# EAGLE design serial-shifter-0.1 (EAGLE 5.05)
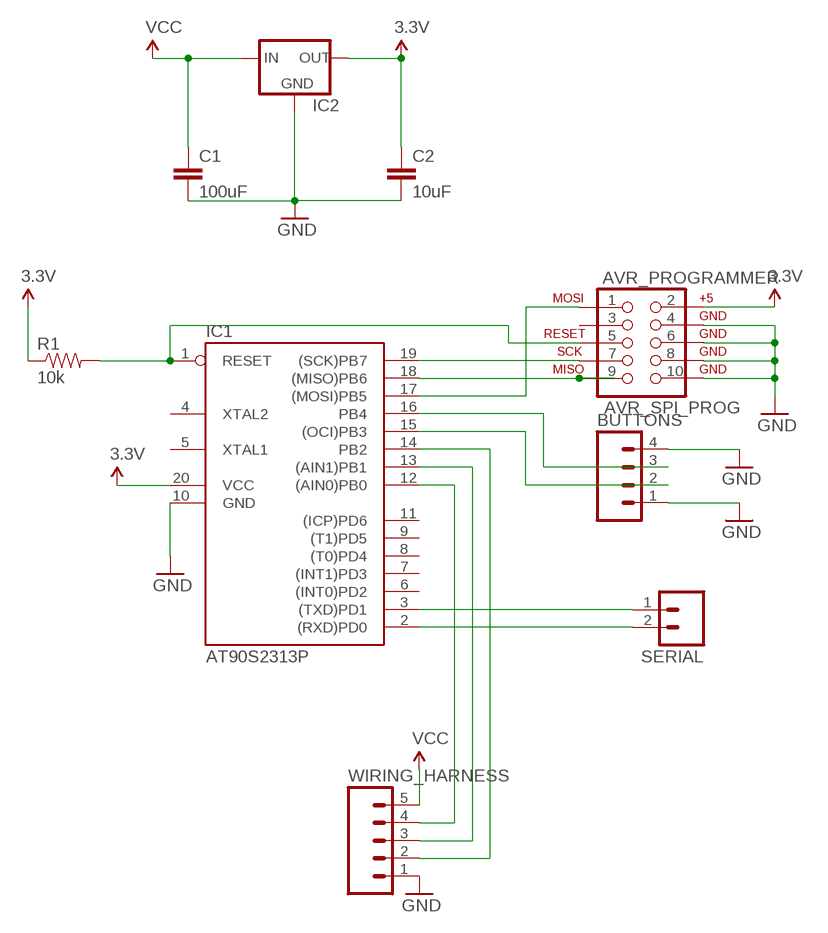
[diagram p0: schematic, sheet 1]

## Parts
AVR_PROGRAMMER  AVR_SPI_PROG  [AVR_ICSP]
BUTTONS  M04PTH  [1X04]
C1  100uF  CAP_  [AXIAL-5MM]
C2  10uF  CAP_  [AXIAL-5MM]
IC1  AT90S2313P  [DIL20]
IC2  V_REG_78XXSINK  [TO220-IGO]
R1  10k  RESISTORPTH1  [AXIAL-0.3]
SERIAL  M02PTH  [1X02]
WIRING_HARNESS  M05PTH  [1X05]

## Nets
3.3V: AVR_PROGRAMMER.2 C2.P$1 IC1.20(VCC) IC2.OUT R1.P$1
AVR_2313A: AVR_PROGRAMMER.5 IC1.1(RESET) R1.P$2
GND: AVR_PROGRAMMER.4 AVR_PROGRAMMER.6 AVR_PROGRAMMER.8 AVR_PROGRAMMER.10 BUTTONS.1 BUTTONS.4 C1.P$2 C2.P$2 IC1.10(GND) IC2.GND WIRING_HARNESS.1
N$1: BUTTONS.3 IC1.16(PB4)
N$2: AVR_PROGRAMMER.1 IC1.17((MOSI)PB5)
N$3: AVR_PROGRAMMER.9 IC1.18((MISO)PB6)
N$4: AVR_PROGRAMMER.7 IC1.19((SCK)PB7)
N$5: IC1.3((TXD)PD1) SERIAL.1
N$6: IC1.2((RXD)PD0) SERIAL.2
N$7: BUTTONS.2 IC1.15((OCI)PB3)
N$8: IC1.12((AIN0)PB0) WIRING_HARNESS.4
N$9: IC1.13((AIN1)PB1) WIRING_HARNESS.3
N$10: IC1.14(PB2) WIRING_HARNESS.2
VCC: C1.P$1 IC2.IN WIRING_HARNESS.5
Unconnected: AVR_PROGRAMMER.3 IC1.4(XTAL2) IC1.5(XTAL1) IC1.6((INT0)PD2) IC1.7((INT1)PD3) IC1.8((T0)PD4) IC1.9((T1)PD5) IC1.11((ICP)PD6)

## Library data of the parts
AVR_PROGRAMMER = SparkFun:AVR_SPI_PROG: AVR ICSP Header This is the standard AVR In Circuit Serial Programming header. Minimal, but includes pin one indicator. Works with standard Olimex programmers. Also look for the 6-pin reduced version. Spark Fun Electronics SKU: PRT-00778
BUTTONS = SparkFun:M04: Header 4 Standard 4-pin 0.1" header. Use with straight break away headers (SKU : PRT-00116), right angle break away headers (PRT-00553), swiss pins (PRT-00743), machine pins (PRT-00117), and female headers (PRT-00115). Molex polarized connector foot print use with SKU : PRT-08231 with associated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
C1 C2 = SparkFun:CAP: Capacitor
IC1 = atmel:AT90S2313: MICROCONTROLLER 2 Kbytes FLASH 128 bytes SRAM 128 bytes EEPROM UART
IC2 = SparkFun:V_REG_78XX: Voltage Regulator Standard 7805 5V regulator. IGO (Input Ground Output). Spark Fun Electronics SKU : COM-00107
R1 = SparkFun:RESISTOR: Resistor
SERIAL = SparkFun:M02: Header 2
WIRING_HARNESS = SparkFun:M05: Header 5 Standard 5-pin 0.1" header. Use with straight break away headers (SKU : PRT-00116), right angle break away headers (PRT-00553), swiss pins (PRT-00743), machine pins (PRT-00117), and female headers (PRT-00115). Molex polarized connector foot print use with SKU : PRT-08230 with associated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

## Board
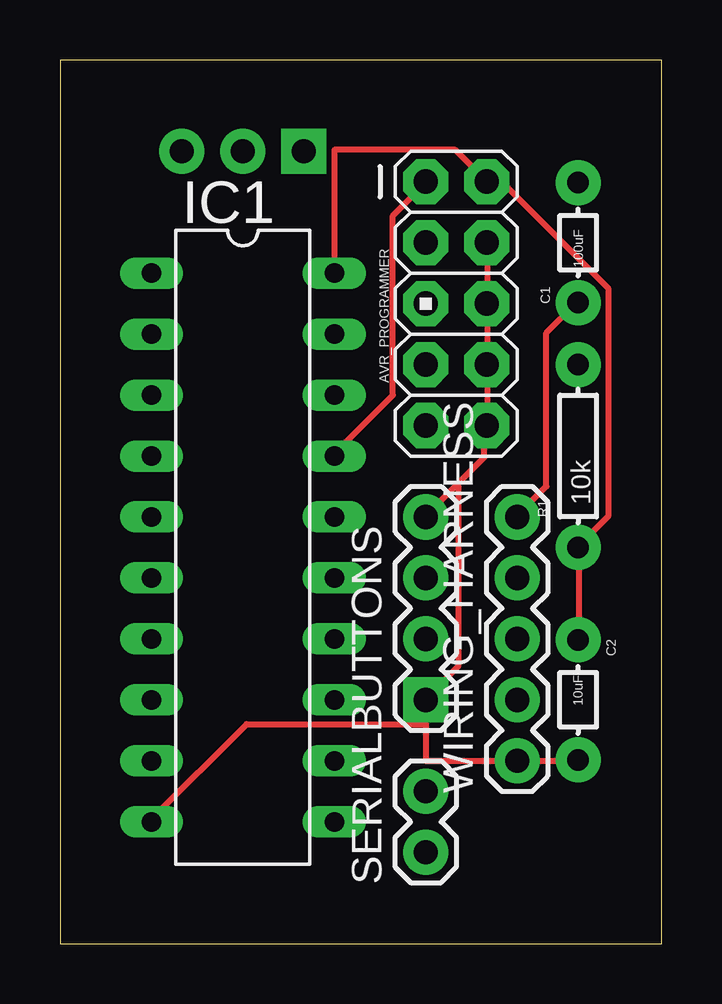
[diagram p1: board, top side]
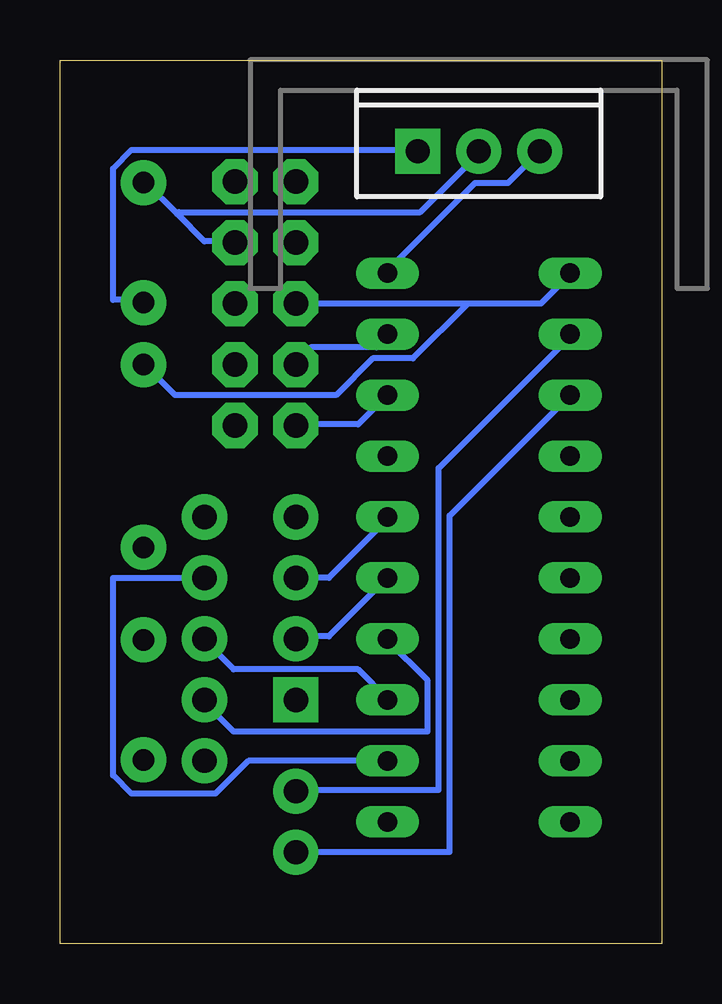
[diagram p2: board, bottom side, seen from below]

Size 25.07 x 36.82 mm. Coordinates in mm from the lower left corner, seen from the top.
Outline: 0,0 25.07,0 25.07,36.82 0,36.82 0,0
Copper layers (1*16): Top 0.035mm / dielectric 1.5mm / Bottom 0.035mm
Design rules "default": minimum track width 10mil, minimum drill 24mil, track to track 8mil, track to pad 8mil, pad to pad 8mil, via to via 8mil, smd to smd 8mil, copper to edge 40mil, drill to drill 8mil, minimum pad ring 10mil, minimum via ring 8mil, stop-mask expansion 4mil, vias tented up to drill 0mil, thermal gap 10mil

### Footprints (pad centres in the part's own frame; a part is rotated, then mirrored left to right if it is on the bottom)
AVR_ICSP = drill 1.016 pad 1.88 octagon: 1 -1.27,5.08; 2 1.27,5.08; 3 -1.27,2.54; 4 1.27,2.54; 5 -1.27,0; 6 1.27,0; 7 -1.27,-2.54; 8 1.27,-2.54; 9 -1.27,-5.08; 10 1.27,-5.08
1X04 = drill 1.016 pad 1.88 square: 1 0,0 | drill 1.016 pad 1.88 round: 2 2.54,0; 3 5.08,0; 4 7.62,0
AXIAL-5MM = drill 0.9 pad 1.88 round: P$1 -2.5,0; P$2 2.5,0
DIL20 = drill 0.813 long: 1 -11.43,-3.81; 2 -8.89,-3.81; 3 -6.35,-3.81; 4 -3.81,-3.81; 5 -1.27,-3.81; 6 1.27,-3.81; 7 3.81,-3.81; 8 6.35,-3.81; 9 8.89,-3.81; 10 11.43,-3.81; 11 11.43,3.81; 12 8.89,3.81; 13 6.35,3.81; 14 3.81,3.81; 15 1.27,3.81; 16 -1.27,3.81; 17 -3.81,3.81; 18 -6.35,3.81; 19 -8.89,3.81; 20 -11.43,3.81
TO220-IGO = drill 1 pad 1.88 round: GND 0,0; OUT 2.54,0 | drill 1 pad 1.88 square: IN -2.54,0
AXIAL-0.3 = drill 0.9 pad 1.88 round: P$1 -3.81,0; P$2 3.81,0
1X02 = drill 1.016 pad 1.88 round: 1 0,0; 2 2.54,0
1X05 = drill 1.016 pad 1.88 round: 1 0,0; 2 2.54,0; 3 5.08,0; 4 7.62,0; 5 10.16,0

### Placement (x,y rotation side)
AVR_PROGRAMMER  16.51,26.67 0 top
BUTTONS  15.24,10.16 90 top
C1  21.59,29.21 90 top
C2  21.59,10.16 270 top
IC1  7.62,16.51 270 top
IC2  7.62,33.02 0 bottom
R1  21.59,20.32 90 top
SERIAL  15.24,3.81 90 top
WIRING_HARNESS  19.05,7.62 90 top

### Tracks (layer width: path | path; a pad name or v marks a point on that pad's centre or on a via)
3.3V
  Top 0.254: C2.P$1 21.64,12.8 21.64,16.46 R1.P$1 21.64,16.61 22.86,17.83 22.86,27.28 18.44,31.7 17.83,31.7 AVR_PROGRAMMER.2 16.46,33.07 11.43,33.07 IC1.20
  Bottom 0.254: IC1.20 11.43,28.04 7.77,31.7 6.4,31.7 IC2.OUT
AVR_2313A
  Bottom 0.254: 8.08,26.67 AVR_PROGRAMMER.5 | 8.08,26.67 5.03,26.67 3.81,27.89 IC1.1 | 8.08,26.67 10.36,24.38 12.04,24.38 13.56,22.86 20.27,22.86 21.49,24.08 R1.P$2
GND
  Top 0.254: C2.P$2 21.49,7.62 WIRING_HARNESS.1 15.24,7.62 15.24,9.14 | 15.24,9.14 7.77,9.14 3.81,5.18 IC1.10 | 15.24,9.14 BUTTONS.1 15.24,10.21 16.61,11.58 16.61,19.05 16.54,19.13 | 16.54,19.13 17.68,20.27 17.68,21.49 AVR_PROGRAMMER.10 17.83,21.64 17.83,24.08 AVR_PROGRAMMER.8 17.83,24.23 17.83,26.67 | 16.54,19.13 15.24,17.83 BUTTONS.4 | 17.83,26.67 17.83,29.11 AVR_PROGRAMMER.4 | 17.83,26.67 AVR_PROGRAMMER.6
  Bottom 0.254: 20.19,30.4 19.05,29.26 17.83,29.26 AVR_PROGRAMMER.4 | 20.19,30.4 21.49,31.7 C1.P$2 | IC2.GND 7.62,32.92 10.06,30.48 20.12,30.48 20.19,30.4
N$1
  Bottom 0.254: BUTTONS.3 13.87,15.24 11.43,17.68 IC1.16
N$2
  Top 0.254: IC1.17 11.43,20.42 13.87,22.86 13.87,30.33 15.24,31.7 AVR_PROGRAMMER.1
N$3
  Bottom 0.254: IC1.18 12.65,21.64 15.24,21.64 AVR_PROGRAMMER.9
N$4
  Bottom 0.254: IC1.19 11.43,25.3 11.89,24.84 14.63,24.84 15.24,24.23 AVR_PROGRAMMER.7
N$5
  Bottom 0.254: IC1.3 8.84,17.83 8.84,3.81 SERIAL.1
N$6
  Bottom 0.254: IC1.2 3.81,25.3 9.3,19.81 9.3,6.4 15.24,6.4 SERIAL.2
N$7
  Bottom 0.254: IC1.15 13.87,12.8 15.24,12.8 BUTTONS.2
N$8
  Bottom 0.254: IC1.12 17.22,7.62 18.59,6.25 22.1,6.25 22.86,7.01 22.86,15.24 WIRING_HARNESS.4
N$9
  Bottom 0.254: IC1.13 11.43,10.21 12.65,11.43 17.83,11.43 19.05,12.65 WIRING_HARNESS.3
N$10
  Bottom 0.254: IC1.14 11.43,12.65 9.75,10.97 9.75,8.84 17.83,8.84 19.05,10.06 WIRING_HARNESS.2
VCC
  Top 0.254: WIRING_HARNESS.5 19.05,17.83 20.27,19.05 20.27,25.45 21.49,26.67 C1.P$1
  Bottom 0.254: IC2.IN 10.21,33.07 22.1,33.07 22.86,32.31 22.86,26.82 21.64,26.82 C1.P$1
